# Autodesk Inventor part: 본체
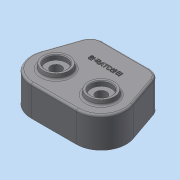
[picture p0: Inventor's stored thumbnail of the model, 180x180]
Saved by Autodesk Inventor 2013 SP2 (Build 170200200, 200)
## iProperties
Created: 2014-12
Part Number: 본체
Material: 일반
Document SubType Name: Modeling
Designer: dgall
Density: 1 g/cm^3
Author: dgall
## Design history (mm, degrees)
sketch "스케치1"
  geometry: L1 (-47, 36)-(47, 36); L2 (47, 36)-(66.565, -20.803); L3 (32.527, -68.527)-(-32.527, -68.527); L4 (-66.565, -20.803)-(-47, 36); L5 (0, 0)-(-56.889, -56.889); L6 (0, 0)-(56.889, -56.889); L7 (0, 0)-(0, -80.453); L8 (61.837, -22.432)-(43.434, 31); L9 (43.434, 31)-(-43.434, 31); L10 (-43.434, 31)-(-61.837, -22.432); L11 (-32.527, -63.527)-(32.527, -63.527); C1 r 24 at (0, 0); C2 r 24 at (-32.527, -32.527); C3 r 24 at (32.527, -32.527); A1 r 36 centre (-32.527, -32.527) between (-66.565, -20.803) and (-32.527, -68.527); A2 r 36 centre (32.527, -32.527) between (32.527, -68.527) and (66.565, -20.803); A3 r 31 centre (-32.527, -32.527) between (-61.837, -22.432) and (-32.527, -63.527); A4 r 31 centre (32.527, -32.527) between (32.527, -63.527) and (61.837, -22.432); A5 r 46 centre (0, 0) between (-32.527, -32.527) and (32.527, -32.527); 2 further points
  constraints: 22 end point, 10 point on circle, 8 centre point, 4 coincident, 3 equal radius, 3 tangent, 2 equal length, 2 parallel, 2 point on line, 1 horizontal, 1 midpoint, 1 perpendicular, 1 vertical alignment, 5 other
  dimensions: "d2" = 48 diameter of C1; "d4" = 36 distance from line of L5.start L1; "d5" = 94 distance of L1.start L1.end; "d6" = 90 deg angle of L5 L6; "d7" = 45 deg angle of L7 L6; "d13" = 36 radius of A1; "d14" = 5 distance between parallel lines of L10 L4; "d26" = 46 radius of A5
extrude "돌출1" new body sketch "스케치1" distance "d15" = 44; taper "d16" = 0 deg
extrude "돌출2" cut sketch "스케치1" distance "d17" = 34; taper "d18" = 0 deg
sketch "스케치2"
  geometry: C1 r 24 at (0, 0); C2 r 24 at (-32.527, -32.527); C3 r 24 at (32.527, -32.527); A1 r 31 centre (-32.527, -32.527) between (-61.837, -22.432) and (-32.527, -63.527) reference; A2 r 31 centre (32.527, -32.527) between (32.527, -63.527) and (61.837, -22.432) reference; 1 further point
  constraints: 3 centre point, 3 coincident, 2 equal radius
  dimensions: "d19" = 48 diameter of C1
extrude "돌출3" join sketch "스케치2" distance "d21" = 11; taper "d22" = 0 deg
sketch "스케치3"
  geometry: C1 r 24 at (0, 0) reference; C2 r 20 at (0, 0); C3 r 10 at (0, 0)
  constraints: 2 centre point
  dimensions: "d23" = 40 diameter of C2; "d25" = 20 diameter of C3
extrude "돌출4" cut sketch "스케치3" distance "d27" = 12; taper "d28" = 0 deg
extrude "돌출5" cut sketch "스케치3" distance "d29" = 15; taper "d30" = 0 deg
sketch "스케치4"
  geometry: C1 r 20 at (-32.527, -32.527); C2 r 20 at (32.527, -32.527); A1 r 36 centre (-32.527, -32.527) between (-66.565, -20.803) and (-32.527, -68.527) reference; A2 r 36 centre (32.527, -32.527) between (32.527, -68.527) and (66.565, -20.803) reference; 1 further point
  constraints: 2 centre point, 2 coincident, 1 equal radius
  dimensions: "d31" = 40 diameter of C1
extrude "돌출6" join sketch "스케치4" distance "d33" = 7; taper "d34" = -10 deg
node "작업 평면1"
sketch "스케치5"
  geometry: L1 (-18.766, 51)-(18.766, 51) reference; L2 (-24, 23)-(24, 23) reference; L3 (41.054, 23)-(89.054, 23) reference; L4 (46.288, 51)-(83.82, 51) reference; L5 (0, 51)-(0, 23); L6 (65.054, 51)-(65.054, 23); L7 (0, 51)-(-15, 51); L8 (-15, 51)-(-15, 44); L9 (-15, 44)-(-7.75, 44); L10 (-7.75, 44)-(-7.75, 34); L11 (-7.75, 34)-(-17.5, 34); L12 (-17.5, 34)-(-17.5, 23); L13 (-17.5, 23)-(0, 23); L14 (65.054, 51)-(50.054, 51); L15 (50.054, 51)-(50.054, 44); L16 (50.054, 44)-(57.304, 44); L17 (57.304, 44)-(57.304, 34); L18 (57.304, 34)-(47.554, 34); L19 (47.554, 34)-(47.554, 23); L20 (47.554, 23)-(65.054, 23); 5 further points
  constraints: 32 end point, 7 perpendicular, 4 midpoint, 4 point on line, 3 parallel, 1 collinear, 1 horizontal
  dimensions: "d36" = 7 distance of L7.end L8.end; "d38" = 10 distance of L9.end L10.end; "d39" = 30 diameter of L8 L5; "d40" = 15.5 diameter of L10 L5; "d41" = 35 diameter of L12 L5; "d42" = 7 distance of L14.end L15.end; "d43" = 10 distance of L16.end L17.end; "d44" = 30 diameter of L15 L6; "d45" = 15.5 diameter of L17 L6; "d46" = 35 diameter of L19 L6
revolve "회전1" stored, may be unused: angle "d47" = 90 deg
revolve "회전2" stored, may be unused: angle "d48" = 90 deg
fillet "모깎기1" dims "d49" = 18
sketch "스케치6"
  geometry: L1 (34.162, 36)-(-34.162, 36) reference; L2 (-61.837, -22.432)-(-43.434, 31) reference; L3 (43.434, 31)-(61.837, -22.432) reference; L4 (32.527, -63.527)-(-32.527, -63.527) reference; A1 r 8 centre (-51.7, 7) between (-54.305, -0.564) and (-49.095, 14.564); A2 r 8 centre (51.7, 7) between (49.095, 14.564) and (54.305, -0.564); A3 r 8 centre (0, -63.527) between (8, -63.527) and (-8, -63.527); 1 further point
  constraints: 8 point on line, 6 point on circle, 3 centre point, 2 equal radius, 1 midpoint
  dimensions: "d50" = 8 radius of A1; "d52" = 29 distance from line of A1.centre L1; "d53" = 29 distance from line of A2.centre L1
extrude "돌출7" join sketch "스케치6" stored distance "d54" = 7; taper "d55" = 0 deg
fillet "모깎기2" dims "d56" = 13
fillet "모깎기3" dims "d57" = 3
hole "구멍1" diameter "d60" = 4.134; stored, may be unused: countersink angle "d64" = 90 deg, drill point angle "d66" = 118 deg; dims "d58" = 10, "d59" = 10, "d61" = 20, "d62" = 4, "d63" = 2, "d65" = 23
hole "구멍2" diameter "d69" = 4.134; stored, may be unused: countersink angle "d73" = 90 deg, drill point angle "d75" = 118 deg; dims "d67" = 10, "d68" = 10, "d70" = 20, "d71" = 4, "d72" = 2, "d74" = 23
hole "구멍3" diameter "d78" = 4.134; stored, may be unused: countersink angle "d82" = 90 deg, drill point angle "d84" = 118 deg; dims "d76" = 10, "d77" = 10, "d79" = 20, "d80" = 4, "d81" = 2, "d83" = 23
fillet "모깎기4" dims "d85" = 3
fillet "모깎기5" dims "d86" = 3
fillet "모깎기6" dims "d87" = 3
fillet "모깎기7" dims "d88" = 0.3
chamfer "모따기1" distance "d89" = 1; stored, may be unused: second distance "d90" = 2, angle "d91" = 45 deg
fillet "모깎기8" dims "d92" = 0.1
fillet "모깎기9" dims "d93" = 3
sketch "스케치7"
  geometry: L1 (34.162, 36)-(-34.162, 36) reference; 2 further points
  constraints: 1 vertical alignment, 1 other
  dimensions: "d94" = 30 distance from line of point (0, 6) L1
feature "엠보싱1" sketch "스케치7" dims "d2" = 48, "d4" = 36, "d5" = 94, "d6" = 90 deg, "d7" = 45 deg, "d13" = 36, "d14" = 5, "d18" = 0, "d26" = 46, "d95" = 1, "d96" = 0
fillet "모깎기10" dims "d97" = 3
fillet "모깎기11" dims "d98" = 3
node "솔리드1"
other parameters: "d12" = 36, "d35" = -36
